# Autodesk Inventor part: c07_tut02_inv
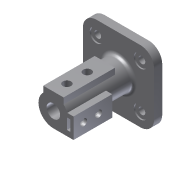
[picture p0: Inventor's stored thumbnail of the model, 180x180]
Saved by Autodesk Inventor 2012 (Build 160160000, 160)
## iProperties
Created: 2010-03
Part Number: c07_tut02_inv
Document SubType Name: Modeling
Designer: CADSoft
Density: 1 g/cm^3
Material: Default
Author: CADSoft
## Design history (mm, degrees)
sketch "Sketch1"
  geometry: 1 further point
sketch "Sketch2"
  geometry: L1 (32.5, 52.5)-(-32.5, 52.5); L2 (-52.5, 32.5)-(-52.5, -32.5); L3 (-32.5, -52.5)-(32.5, -52.5); L4 (52.5, -32.5)-(52.5, 32.5); A1 r 20 centre (32.5, 32.5) between (52.5, 32.5) and (32.5, 52.5); A2 r 20 centre (-32.5, 32.5) between (-32.5, 52.5) and (-52.5, 32.5); A3 r 20 centre (-32.5, -32.5) between (-52.5, -32.5) and (-32.5, -52.5); A4 r 20 centre (32.5, -32.5) between (32.5, -52.5) and (52.5, -32.5); 4 further points
  constraints: 8 end point, 8 point on circle, 8 tangent, 6 point on line, 4 centre point, 3 equal radius, 3 perpendicular, 1 other
  dimensions: "d3" = 105 distance of point (52.5, 52.5) point (-52.5, 52.5); "d4" = 105 distance of point (52.5, -52.5) point (52.5, 52.5); "d6" = 52.5 distance from line of L1 point (0, 0); "d7" = 52.5 distance from line of L4 point (0, 0); "d8" = 20 radius of A1
extrude "Extrusion1" new body sketch "Sketch2" distance "d9" = 12; taper "d10" = 0 deg
hole "Hole1" diameter "d13" = 10; stored, may be unused: countersink angle "d17" = 90 deg, drill point angle "d19" = 118 deg; dims "d11" = 10, "d12" = 10, "d14" = 6, "d15" = 20, "d16" = 2, "d18" = 8
hole "Hole2" diameter "d22" = 10; stored, may be unused: countersink angle "d26" = 90 deg, drill point angle "d28" = 118 deg; dims "d20" = 10, "d21" = 10, "d23" = 6, "d24" = 20, "d25" = 2, "d27" = 8
hole "Hole3" diameter "d31" = 10; stored, may be unused: countersink angle "d35" = 90 deg, drill point angle "d37" = 118 deg; dims "d29" = 10, "d30" = 10, "d32" = 6, "d33" = 20, "d34" = 2, "d36" = 8
hole "Hole4" diameter "d40" = 10; stored, may be unused: countersink angle "d44" = 90 deg, drill point angle "d46" = 118 deg; dims "d38" = 10, "d39" = 10, "d41" = 6, "d42" = 20, "d43" = 2, "d45" = 8
sketch "Sketch3"
  geometry: C1 r 22 at (0, 0); 1 further point
  constraints: 1 centre point, 1 coincident
  dimensions: "d47" = 44 diameter of C1
extrude "Extrusion2" join sketch "Sketch3" distance "d48" = 96; taper "d49" = 0 deg
sketch "Sketch4"
  geometry: L1 (-15, 25)-(15, 25); L2 (15, 25)-(15, 16.093); L3 (-14.745, 16.328)-(-15, 16.093); L4 (-15, 16.093)-(-15, 25); A1 r 22 centre (0, 0) between (15, 16.093) and (-15, 16.093); 1 further point
  constraints: 8 end point, 4 point on circle, 2 vertical, 1 centre point, 1 coincident
  dimensions: "d50" = 30 distance of L1.start L1.end; "d52" = 15 distance from line of point (0, 0) L4; "d53" = 25 distance from line of point (0, 0) L1
extrude "Extrusion3" join sketch "Sketch4" distance "d54" = 76; taper "d55" = 0 deg
sketch "Sketch5"
  geometry: L1 (0, -22)-(29.709, -22); L2 (29.709, -22)-(29.709, 8); L3 (29.709, 8)-(20.494, 8); A1 r 22 centre (0, 0) between (0, -22) and (20.494, 8); 1 further point
  constraints: 6 end point, 2 point on circle, 1 centre point, 1 coincident
  dimensions: "d61" = 30 distance of L1.end L2.end
extrude "Extrusion4" join sketch "Sketch5" distance "d62" = 57; taper "d63" = 0 deg
sketch "Sketch6"
  geometry: L1 (20, 2)-(25, 2); L2 (25, 2)-(25, -14); L3 (25, -14)-(20, -14); L4 (20, -14)-(20, 2); A1 r 22 centre (0, 0) between (20.494, 8) and (15, 16.093) reference
  constraints: 8 end point
  dimensions: "d64" = 2 distance from line of A1.centre L1; "d66" = 25 distance from line of L2 A1.centre; "d67" = 5 distance of L2.end L3.end; "d68" = 16 distance of L1.end L2.end
extrude "Extrusion5" cut sketch "Sketch6" distance "d69" = 50; taper "d70" = 0 deg
hole "Hole5" diameter "d73" = 20; stored, may be unused: countersink angle "d77" = 90 deg, drill point angle "d79" = 0 deg; dims "d71" = 10, "d72" = 10, "d74" = 6, "d75" = 20, "d76" = 2, "d78" = 96
hole "Hole6" diameter "d82" = 12; stored, may be unused: countersink angle "d86" = 90 deg, drill point angle "d88" = 118 deg; dims "d80" = 20, "d81" = 15, "d83" = 6, "d84" = 20, "d85" = 2, "d87" = 96
hole "Hole7" diameter "d91" = 12; stored, may be unused: countersink angle "d95" = 90 deg, drill point angle "d97" = 118 deg; dims "d89" = 15, "d90" = 50, "d92" = 6, "d93" = 20, "d94" = 2, "d96" = 96
hole "Hole8" diameter "d100" = 10; stored, may be unused: countersink angle "d104" = 90 deg, drill point angle "d106" = 118 deg; dims "d98" = 15, "d99" = 15, "d101" = 6, "d102" = 20, "d103" = 2, "d105" = 96
hole "Hole9" diameter "d109" = 10; stored, may be unused: countersink angle "d113" = 90 deg, drill point angle "d115" = 118 deg; dims "d107" = 15, "d108" = 37, "d110" = 6, "d111" = 20, "d112" = 2, "d114" = 96
fillet "Fillet1" dims "d116" = 5
body "Solid1"
